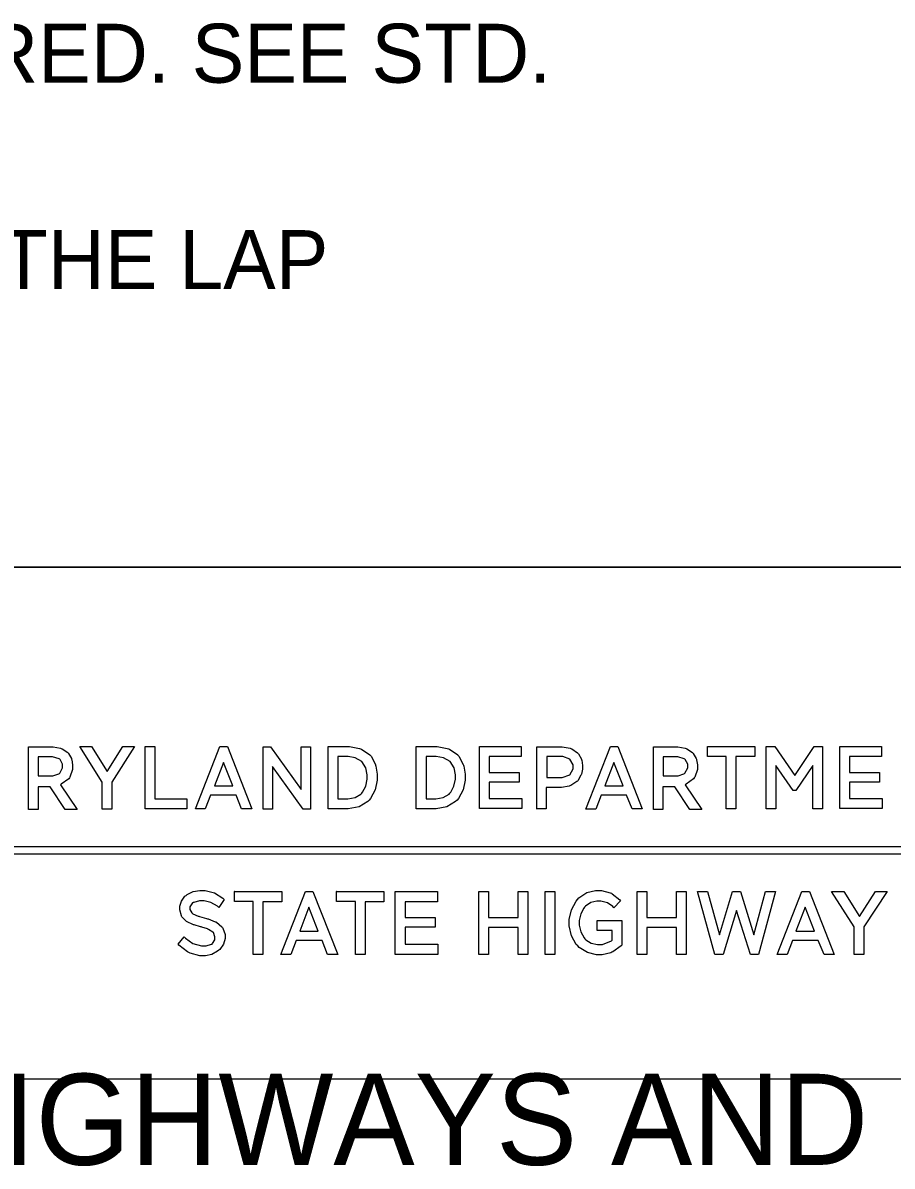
# Model space of a CAD drawing. Extents: x -32.9 to -15.8, y -6.5 to 4.5.
# Drawn here: x -19.012 to -18.128, y -5.338 to -4.175 of the extents above; entities that cross this region are included whole.
import ezdxf

# ---------------------------------------------------------------- set-up
doc = ezdxf.new("R2010")
doc.units = 0
for name, color, linetype in [('BORD-LINE', 7, 'Continuous'), ('Level 13', 7, 'Continuous'), ('MSHA-LOGO', 7, 'Continuous'), ('TTLB-TEXT', 7, 'Continuous'), ('USER-LINE', 7, 'Continuous')]:
    doc.layers.add(name, color=color, linetype=linetype)

msp = doc.modelspace()

# ---------------------------------------------------------------- linework, layer by layer
at = {"layer": 'BORD-LINE'}
msp.add_line((-16.1409, -4.729), (-20.6138, -4.729), dxfattribs=at)
at = {"layer": 'MSHA-LOGO'}
for points in [[(-19.0063, -4.9752), (-19.0063, -4.9117), (-18.984, -4.9117), (-18.9812, -4.9117), (-18.9737, -4.9131), (-18.9729, -4.9133), (-18.9722, -4.9136), (-18.9664, -4.9175), (-18.966, -4.9179), (-18.9656, -4.9184), (-18.9627, -4.9236), (-18.9624, -4.9242), (-18.9623, -4.9248), (-18.9614, -4.93), (-18.9614, -4.9318), (-18.9614, -4.9346), (-18.9642, -4.9424), (-18.9647, -4.9433), (-18.9653, -4.9441), (-18.9729, -4.9498), (-18.9739, -4.9502), (-18.9569, -4.9755), (-18.969, -4.9755), (-18.9843, -4.9522), (-18.9965, -4.9522), (-18.9965, -4.9755), (-19.0063, -4.9755)], [(-18.9215, -4.9476), (-18.9215, -4.9752), (-18.9313, -4.9752), (-18.9313, -4.9476), (-18.9542, -4.9114), (-18.9421, -4.9114), (-18.9264, -4.9367), (-18.9104, -4.9114), (-18.8986, -4.9114)], [(-18.8875, -4.9114), (-18.8777, -4.9114), (-18.8777, -4.9647), (-18.8453, -4.9647), (-18.8453, -4.9749), (-18.8875, -4.9749)], [(-18.8116, -4.9114), (-18.804, -4.9114), (-18.7792, -4.9749), (-18.7896, -4.9749), (-18.7952, -4.9607), (-18.8211, -4.9607), (-18.8266, -4.9749), (-18.8364, -4.9749)], [(-18.7268, -4.9752), (-18.7582, -4.9318), (-18.7582, -4.9752), (-18.7677, -4.9752), (-18.7677, -4.9117), (-18.7602, -4.9117), (-18.7288, -4.9551), (-18.7288, -4.9117), (-18.7193, -4.9117), (-18.7193, -4.9752)], [(-18.7013, -4.9114), (-18.6836, -4.9114), (-18.6798, -4.9114), (-18.6696, -4.9133), (-18.6685, -4.9137), (-18.6675, -4.9141), (-18.6591, -4.9198), (-18.6584, -4.9206), (-18.6578, -4.9213), (-18.6534, -4.9295), (-18.6532, -4.9304), (-18.6529, -4.9313), (-18.6515, -4.9396), (-18.6515, -4.9423), (-18.6515, -4.9456), (-18.6536, -4.9553), (-18.6583, -4.9644), (-18.6597, -4.966), (-18.6611, -4.9674), (-18.6701, -4.9726), (-18.681, -4.9749), (-18.6846, -4.9749), (-18.7013, -4.9749)], [(-18.6119, -4.9114), (-18.5943, -4.9114), (-18.5905, -4.9114), (-18.5803, -4.9133), (-18.5792, -4.9137), (-18.5782, -4.9141), (-18.5697, -4.9198), (-18.5691, -4.9206), (-18.5685, -4.9213), (-18.5641, -4.9295), (-18.5638, -4.9304), (-18.5636, -4.9313), (-18.5622, -4.9396), (-18.5622, -4.9423), (-18.5622, -4.9456), (-18.5642, -4.9553), (-18.569, -4.9644), (-18.5704, -4.966), (-18.5718, -4.9674), (-18.5807, -4.9726), (-18.5916, -4.9749), (-18.5953, -4.9749), (-18.6119, -4.9749)], [(-18.5475, -4.9114), (-18.5053, -4.9114), (-18.5053, -4.9216), (-18.5376, -4.9216), (-18.5376, -4.9377), (-18.5072, -4.9377), (-18.5072, -4.9476), (-18.5376, -4.9476), (-18.5376, -4.9643), (-18.5043, -4.9643), (-18.5043, -4.9745), (-18.5475, -4.9745)], [(-18.4892, -4.9752), (-18.4892, -4.9117), (-18.4663, -4.9117), (-18.4634, -4.9117), (-18.4554, -4.9131), (-18.4545, -4.9133), (-18.4537, -4.9137), (-18.4477, -4.9178), (-18.4473, -4.9183), (-18.4469, -4.9188), (-18.4439, -4.9243), (-18.4437, -4.9249), (-18.4436, -4.9254), (-18.4427, -4.9307), (-18.4427, -4.9324), (-18.4427, -4.9343), (-18.4438, -4.9394), (-18.4441, -4.94), (-18.4443, -4.9405), (-18.4476, -4.9461), (-18.448, -4.9466), (-18.4484, -4.947), (-18.4547, -4.9511), (-18.4555, -4.9515), (-18.4563, -4.9518), (-18.4641, -4.9531), (-18.4666, -4.9531), (-18.4797, -4.9531), (-18.4797, -4.9749), (-18.4892, -4.9749)], [(-18.4143, -4.9114), (-18.4067, -4.9114), (-18.3819, -4.9749), (-18.3924, -4.9749), (-18.3979, -4.961), (-18.4238, -4.961), (-18.4293, -4.9752), (-18.4395, -4.9752)], [(-18.3707, -4.9752), (-18.3707, -4.9117), (-18.3485, -4.9117), (-18.3457, -4.9117), (-18.3382, -4.9131), (-18.3374, -4.9133), (-18.3366, -4.9136), (-18.3309, -4.9175), (-18.3305, -4.9179), (-18.3301, -4.9184), (-18.3272, -4.9236), (-18.3269, -4.9242), (-18.3268, -4.9248), (-18.3259, -4.93), (-18.3259, -4.9318), (-18.3259, -4.9346), (-18.3286, -4.9424), (-18.3292, -4.9433), (-18.3298, -4.9441), (-18.3374, -4.9498), (-18.3384, -4.9502), (-18.3213, -4.9755), (-18.3335, -4.9755), (-18.3488, -4.9522), (-18.3609, -4.9522), (-18.3609, -4.9755), (-18.3707, -4.9755)], [(-18.3155, -4.9114), (-18.2673, -4.9114), (-18.2673, -4.9216), (-18.2867, -4.9216), (-18.2867, -4.9749), (-18.2965, -4.9749), (-18.2965, -4.9216), (-18.3155, -4.9216)], [(-18.2559, -4.9114), (-18.2471, -4.9114), (-18.2268, -4.941), (-18.2071, -4.9114), (-18.1986, -4.9114), (-18.1986, -4.9749), (-18.2084, -4.9749), (-18.2084, -4.9308), (-18.2258, -4.9561), (-18.2284, -4.9561), (-18.2461, -4.9308), (-18.2461, -4.9749), (-18.2559, -4.9749)], [(-18.1809, -4.9114), (-18.1387, -4.9114), (-18.1387, -4.9216), (-18.1711, -4.9216), (-18.1711, -4.9377), (-18.1407, -4.9377), (-18.1407, -4.9476), (-18.1711, -4.9476), (-18.1711, -4.9643), (-18.1378, -4.9643), (-18.1378, -4.9745), (-18.1809, -4.9745)], [(-18.9965, -4.9219), (-18.9965, -4.9413), (-18.9837, -4.9413), (-18.9815, -4.9413), (-18.9755, -4.9391), (-18.9749, -4.9387), (-18.9744, -4.9383), (-18.9716, -4.9329), (-18.9716, -4.9311), (-18.9716, -4.9294), (-18.9741, -4.9246), (-18.9745, -4.9242), (-18.975, -4.9238), (-18.9818, -4.9219), (-18.984, -4.9219)], [(-18.8171, -4.9515), (-18.7985, -4.9515), (-18.808, -4.9275)], [(-18.6915, -4.9219), (-18.6915, -4.9647), (-18.6839, -4.9647), (-18.6815, -4.9647), (-18.6741, -4.9632), (-18.6682, -4.9597), (-18.6673, -4.9587), (-18.6664, -4.9577), (-18.6631, -4.9516), (-18.6617, -4.9446), (-18.6617, -4.9423), (-18.6617, -4.94), (-18.663, -4.9332), (-18.6671, -4.9267), (-18.674, -4.9228), (-18.6812, -4.9216), (-18.6836, -4.9216), (-18.6915, -4.9216)], [(-18.6018, -4.9219), (-18.6018, -4.9647), (-18.5943, -4.9647), (-18.5918, -4.9647), (-18.5845, -4.9632), (-18.5785, -4.9597), (-18.5776, -4.9587), (-18.5767, -4.9577), (-18.5735, -4.9516), (-18.572, -4.9446), (-18.572, -4.9423), (-18.572, -4.94), (-18.5734, -4.9332), (-18.5775, -4.9267), (-18.5843, -4.9228), (-18.5915, -4.9216), (-18.5939, -4.9216), (-18.6018, -4.9216)], [(-18.4791, -4.9216), (-18.4791, -4.9429), (-18.466, -4.9429), (-18.4634, -4.9429), (-18.4557, -4.9402), (-18.4522, -4.9341), (-18.4522, -4.9321), (-18.4522, -4.9301), (-18.4555, -4.9242), (-18.4629, -4.9216), (-18.4653, -4.9216)], [(-18.4202, -4.9515), (-18.4015, -4.9515), (-18.411, -4.9275)], [(-18.3606, -4.9219), (-18.3606, -4.9413), (-18.3478, -4.9413), (-18.3456, -4.9413), (-18.3396, -4.9391), (-18.339, -4.9387), (-18.3385, -4.9383), (-18.3357, -4.9329), (-18.3357, -4.9311), (-18.3357, -4.9294), (-18.3382, -4.9246), (-18.3387, -4.9242), (-18.3392, -4.9238), (-18.3459, -4.9219), (-18.3482, -4.9219)], [(-19.1447, -5.0131), (-17.028, -5.0131), (-17.028, -5.021), (-19.1447, -5.021)], [(-18.8186, -5.1004), (-18.8189, -5.1001), (-18.8231, -5.0974), (-18.8237, -5.0972), (-18.8242, -5.097), (-18.8301, -5.0951), (-18.8307, -5.0949), (-18.8314, -5.0948), (-18.8377, -5.0929), (-18.8384, -5.0927), (-18.839, -5.0924), (-18.8449, -5.0898), (-18.8454, -5.0895), (-18.846, -5.0892), (-18.8502, -5.0846), (-18.8505, -5.084), (-18.8508, -5.0835), (-18.8524, -5.0776), (-18.8524, -5.0757), (-18.8524, -5.0739), (-18.8508, -5.0686), (-18.8471, -5.0637), (-18.846, -5.0628), (-18.845, -5.0619), (-18.8389, -5.0589), (-18.832, -5.0577), (-18.8297, -5.0577), (-18.8266, -5.0577), (-18.817, -5.0601), (-18.8087, -5.0655), (-18.8074, -5.067), (-18.8128, -5.075), (-18.814, -5.0739), (-18.8207, -5.07), (-18.8277, -5.0683), (-18.8301, -5.0683), (-18.8322, -5.0683), (-18.8382, -5.0699), (-18.8387, -5.0702), (-18.8393, -5.0705), (-18.8422, -5.0746), (-18.8422, -5.076), (-18.8422, -5.0773), (-18.84, -5.0807), (-18.8396, -5.0811), (-18.8392, -5.0815), (-18.8337, -5.0839), (-18.8329, -5.084), (-18.8322, -5.0842), (-18.8251, -5.0863), (-18.8243, -5.0866), (-18.8235, -5.0868), (-18.8163, -5.0896), (-18.8157, -5.0898), (-18.8151, -5.0901), (-18.8095, -5.0949), (-18.809, -5.0956), (-18.8086, -5.0962), (-18.8064, -5.1027), (-18.8064, -5.1049), (-18.8064, -5.1068), (-18.8081, -5.1125), (-18.8118, -5.1178), (-18.8128, -5.1187), (-18.8139, -5.1196), (-18.8199, -5.1228), (-18.8263, -5.1242), (-18.8285, -5.1242), (-18.8321, -5.1242), (-18.842, -5.1215), (-18.8432, -5.1209), (-18.8444, -5.1204), (-18.8534, -5.1134), (-18.854, -5.1126), (-18.848, -5.1049), (-18.8467, -5.1064), (-18.8391, -5.1118), (-18.8304, -5.1142), (-18.8275, -5.1142), (-18.8255, -5.1142), (-18.82, -5.1126), (-18.8195, -5.1123), (-18.819, -5.1119), (-18.8166, -5.1079), (-18.8166, -5.1065), (-18.8166, -5.105), (-18.8182, -5.1007)], [(-18.7972, -5.0587), (-18.7486, -5.0587), (-18.7486, -5.0693), (-18.7678, -5.0693), (-18.7678, -5.1229), (-18.7777, -5.1229), (-18.7777, -5.0689), (-18.7968, -5.0689), (-18.7968, -5.0587)], [(-18.7246, -5.0587), (-18.717, -5.0587), (-18.6917, -5.1229), (-18.7023, -5.1229), (-18.7077, -5.1088), (-18.7339, -5.1088), (-18.7393, -5.1229), (-18.7496, -5.1229)], [(-18.6933, -5.0587), (-18.6447, -5.0587), (-18.6447, -5.0693), (-18.6639, -5.0693), (-18.6639, -5.1229), (-18.6738, -5.1229), (-18.6738, -5.0689), (-18.693, -5.0689), (-18.693, -5.0587)], [(-18.6332, -5.0587), (-18.5904, -5.0587), (-18.5904, -5.0693), (-18.6233, -5.0693), (-18.6233, -5.0853), (-18.5927, -5.0853), (-18.5927, -5.0953), (-18.6233, -5.0953), (-18.6233, -5.1123), (-18.5898, -5.1123), (-18.5898, -5.1229), (-18.6332, -5.1229)], [(-18.5083, -5.0956), (-18.5384, -5.0956), (-18.5384, -5.1229), (-18.5483, -5.1229), (-18.5483, -5.0587), (-18.5384, -5.0587), (-18.5384, -5.0853), (-18.5083, -5.0853), (-18.5083, -5.0587), (-18.4984, -5.0587), (-18.4984, -5.1229), (-18.5083, -5.1229)], [(-18.4808, -5.0587), (-18.4709, -5.0587), (-18.4709, -5.1229), (-18.4808, -5.1229)], [(-18.4278, -5.0885), (-18.4029, -5.0885), (-18.4029, -5.1133), (-18.4035, -5.1141), (-18.4118, -5.1202), (-18.4128, -5.1206), (-18.4138, -5.1211), (-18.4226, -5.1232), (-18.4256, -5.1232), (-18.4286, -5.1232), (-18.4378, -5.121), (-18.4462, -5.1157), (-18.4476, -5.1142), (-18.4491, -5.1127), (-18.4541, -5.1038), (-18.4562, -5.0938), (-18.4562, -5.0904), (-18.4562, -5.0872), (-18.4541, -5.0776), (-18.4493, -5.0686), (-18.4479, -5.067), (-18.4465, -5.0654), (-18.4383, -5.0599), (-18.4297, -5.0577), (-18.4268, -5.0577), (-18.4235, -5.0577), (-18.4145, -5.0601), (-18.4134, -5.0606), (-18.4125, -5.0611), (-18.4047, -5.0675), (-18.4042, -5.0683), (-18.4109, -5.0754), (-18.4118, -5.0742), (-18.4173, -5.0703), (-18.424, -5.0686), (-18.4262, -5.0686), (-18.4282, -5.0686), (-18.4344, -5.0701), (-18.4397, -5.0737), (-18.4406, -5.0747), (-18.4415, -5.0757), (-18.4446, -5.0816), (-18.446, -5.0885), (-18.446, -5.0908), (-18.446, -5.0931), (-18.4446, -5.1), (-18.4412, -5.1061), (-18.4403, -5.1071), (-18.4393, -5.1081), (-18.4338, -5.1115), (-18.4276, -5.1129), (-18.4256, -5.1129), (-18.4223, -5.1129), (-18.4134, -5.1092), (-18.4125, -5.1084), (-18.4125, -5.0985), (-18.4278, -5.0985)], [(-18.3473, -5.0956), (-18.3773, -5.0956), (-18.3773, -5.1229), (-18.3872, -5.1229), (-18.3872, -5.0587), (-18.3773, -5.0587), (-18.3773, -5.0853), (-18.3473, -5.0853), (-18.3473, -5.0587), (-18.3374, -5.0587), (-18.3374, -5.1229), (-18.3473, -5.1229)], [(-18.2636, -5.1229), (-18.2719, -5.1229), (-18.286, -5.0782), (-18.2997, -5.1229), (-18.308, -5.1229), (-18.3259, -5.0587), (-18.3157, -5.0587), (-18.3035, -5.103), (-18.2901, -5.0587), (-18.2821, -5.0587), (-18.2684, -5.103), (-18.2565, -5.0587), (-18.2466, -5.0587)], [(-18.2195, -5.0587), (-18.2118, -5.0587), (-18.1866, -5.1229), (-18.1971, -5.1229), (-18.2029, -5.1088), (-18.2291, -5.1088), (-18.2345, -5.1229), (-18.2447, -5.1229)], [(-18.1565, -5.0949), (-18.1565, -5.1229), (-18.1664, -5.1229), (-18.1664, -5.0949), (-18.1894, -5.0587), (-18.177, -5.0587), (-18.161, -5.0844), (-18.1447, -5.0587), (-18.1329, -5.0587)], [(-18.7304, -5.0991), (-18.7115, -5.0991), (-18.7211, -5.0747)], [(-18.2256, -5.0991), (-18.2067, -5.0991), (-18.2163, -5.0747)]]:
    msp.add_lwpolyline(points, close=True, dxfattribs=at)
at = {"layer": 'USER-LINE'}
msp.add_lwpolyline([(-16.8918, -5.2497), (-19.8629, -5.2497), (-19.8629, -4.729), (-16.8918, -4.729)], close=True, dxfattribs=at)

# ---------------------------------------------------------------- texts
at = {"layer": 'Level 13'}
for s, p in [('WHEN BARRIER IS CONSTRUCTED USING THE SLIP FORM METHOD, DIAGONAL NO. 4 BARS ARE REQUIRED. SEE STD. ', (-23.0939, -4.236)), ('10. THE CONTRACTOR MAY CONSTRUCT THE VERTICAL NO. 5 BARS AS SHOWN ON THIS STANDARD OR USE THE LAP', (-23.3339, -4.446))]:
    msp.add_text(s, height=0.06001, dxfattribs=at).set_placement(p)
at = {"layer": 'TTLB-TEXT'}
msp.add_text('STANDARDS FOR HIGHWAYS AND INCIDENTAL STRUCTURES', height=0.09269, dxfattribs=at).set_placement((-20.218, -5.337))

doc.saveas('drawing.dxf')
